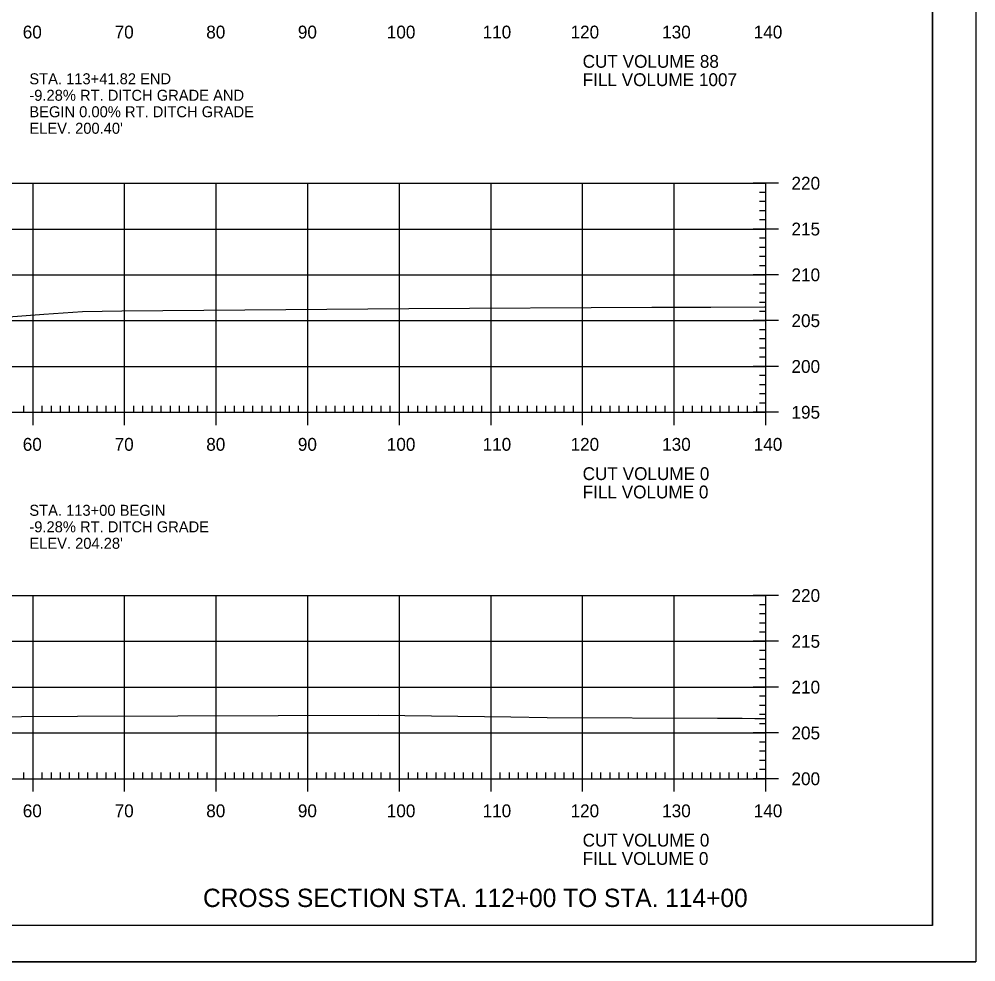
# Model space of a CAD drawing. Extents: x 1312042 to 1371461, y 379929 to 1834241.
# Drawn here: x 1371356.8 to 1371461.2, y 379928.9 to 380031.8 of the extents above; entities that cross this region are included whole.
import ezdxf

# ---------------------------------------------------------------- set-up
doc = ezdxf.new("R2010")
doc.units = 0
for name, color, linetype in [('R_Axis', 7, 'Continuous'), ('R_Axis Annot', 7, 'Continuous'), ('R_Border', 7, 'Continuous'), ('R_Draft', 7, 'Continuous'), ('R_Drive', 7, 'Continuous'), ('R_Exist Surface', 7, 'Continuous'), ('R_Grid', 7, 'Continuous'), ('R_No Plot', 7, 'Continuous')]:
    doc.layers.add(name, color=color, linetype=linetype)

msp = doc.modelspace()

# ---------------------------------------------------------------- linework, layer by layer
at = {"layer": 'R_Axis'}
for p, q in [((1371439.68, 380013.91), (1371436.88, 380013.91)), ((1371438.28, 379988.91), (1371438.28, 380013.91)), ((1371438.28, 380012.91), (1371437.58, 380012.91)), ((1371438.28, 380011.91), (1371437.58, 380011.91)), ((1371438.28, 380010.91), (1371437.58, 380010.91)), ((1371438.28, 380009.91), (1371437.58, 380009.91)), ((1371439.68, 380008.91), (1371436.88, 380008.91)), ((1371438.28, 380007.91), (1371437.58, 380007.91)), ((1371438.28, 380006.91), (1371437.58, 380006.91)), ((1371438.28, 380005.91), (1371437.58, 380005.91)), ((1371438.28, 380004.91), (1371437.58, 380004.91)), ((1371439.68, 380003.91), (1371436.88, 380003.91)), ((1371438.28, 380002.91), (1371437.58, 380002.91)), ((1371438.28, 380001.91), (1371437.58, 380001.91)), ((1371438.28, 380000.91), (1371437.58, 380000.91)), ((1371438.28, 379999.91), (1371437.58, 379999.91)), ((1371439.68, 379998.91), (1371436.88, 379998.91)), ((1371438.28, 379997.91), (1371437.58, 379997.91)), ((1371438.28, 379996.91), (1371437.58, 379996.91)), ((1371438.28, 379995.91), (1371437.58, 379995.91)), ((1371439.68, 379993.91), (1371436.88, 379993.91)), ((1371438.28, 379994.91), (1371437.58, 379994.91)), ((1371438.28, 379992.91), (1371437.58, 379992.91)), ((1371438.28, 379991.91), (1371437.58, 379991.91)), ((1371438.28, 379990.91), (1371437.58, 379990.91)), ((1371358.28, 379987.51), (1371358.28, 379990.31)), ((1371368.28, 379987.51), (1371368.28, 379990.31)), ((1371378.28, 379987.51), (1371378.28, 379990.31)), ((1371388.28, 379987.51), (1371388.28, 379990.31)), ((1371398.28, 379987.51), (1371398.28, 379990.31)), ((1371408.28, 379987.51), (1371408.28, 379990.31)), ((1371418.28, 379987.51), (1371418.28, 379990.31)), ((1371428.28, 379987.51), (1371428.28, 379990.31)), ((1371438.28, 379989.91), (1371437.58, 379989.91)), ((1371438.28, 379987.51), (1371438.28, 379990.31)), ((1371158.28, 379988.91), (1371438.28, 379988.91)), ((1371357.28, 379988.91), (1371357.28, 379989.61)), ((1371359.28, 379988.91), (1371359.28, 379989.61)), ((1371360.28, 379988.91), (1371360.28, 379989.61)), ((1371361.28, 379988.91), (1371361.28, 379989.61)), ((1371362.28, 379988.91), (1371362.28, 379989.61)), ((1371363.28, 379988.91), (1371363.28, 379989.61)), ((1371364.28, 379988.91), (1371364.28, 379989.61)), ((1371365.28, 379988.91), (1371365.28, 379989.61)), ((1371366.28, 379988.91), (1371366.28, 379989.61)), ((1371367.28, 379988.91), (1371367.28, 379989.61)), ((1371369.28, 379988.91), (1371369.28, 379989.61)), ((1371370.28, 379988.91), (1371370.28, 379989.61)), ((1371371.28, 379988.91), (1371371.28, 379989.61)), ((1371372.28, 379988.91), (1371372.28, 379989.61)), ((1371373.28, 379988.91), (1371373.28, 379989.61)), ((1371374.28, 379988.91), (1371374.28, 379989.61)), ((1371375.28, 379988.91), (1371375.28, 379989.61)), ((1371376.28, 379988.91), (1371376.28, 379989.61)), ((1371377.28, 379988.91), (1371377.28, 379989.61)), ((1371379.28, 379988.91), (1371379.28, 379989.61)), ((1371380.28, 379988.91), (1371380.28, 379989.61)), ((1371381.28, 379988.91), (1371381.28, 379989.61)), ((1371382.28, 379988.91), (1371382.28, 379989.61)), ((1371383.28, 379988.91), (1371383.28, 379989.61)), ((1371384.28, 379988.91), (1371384.28, 379989.61)), ((1371385.28, 379988.91), (1371385.28, 379989.61)), ((1371386.28, 379988.91), (1371386.28, 379989.61)), ((1371387.28, 379988.91), (1371387.28, 379989.61)), ((1371389.28, 379988.91), (1371389.28, 379989.61)), ((1371390.28, 379988.91), (1371390.28, 379989.61)), ((1371391.28, 379988.91), (1371391.28, 379989.61)), ((1371392.28, 379988.91), (1371392.28, 379989.61)), ((1371393.28, 379988.91), (1371393.28, 379989.61)), ((1371394.28, 379988.91), (1371394.28, 379989.61)), ((1371395.28, 379988.91), (1371395.28, 379989.61)), ((1371396.28, 379988.91), (1371396.28, 379989.61)), ((1371397.28, 379988.91), (1371397.28, 379989.61)), ((1371399.28, 379988.91), (1371399.28, 379989.61)), ((1371400.28, 379988.91), (1371400.28, 379989.61)), ((1371401.28, 379988.91), (1371401.28, 379989.61)), ((1371402.28, 379988.91), (1371402.28, 379989.61)), ((1371403.28, 379988.91), (1371403.28, 379989.61)), ((1371404.28, 379988.91), (1371404.28, 379989.61)), ((1371405.28, 379988.91), (1371405.28, 379989.61)), ((1371406.28, 379988.91), (1371406.28, 379989.61)), ((1371407.28, 379988.91), (1371407.28, 379989.61)), ((1371409.28, 379988.91), (1371409.28, 379989.61)), ((1371410.28, 379988.91), (1371410.28, 379989.61)), ((1371411.28, 379988.91), (1371411.28, 379989.61)), ((1371412.28, 379988.91), (1371412.28, 379989.61)), ((1371413.28, 379988.91), (1371413.28, 379989.61)), ((1371414.28, 379988.91), (1371414.28, 379989.61)), ((1371415.28, 379988.91), (1371415.28, 379989.61)), ((1371416.28, 379988.91), (1371416.28, 379989.61)), ((1371417.28, 379988.91), (1371417.28, 379989.61)), ((1371419.28, 379988.91), (1371419.28, 379989.61)), ((1371420.28, 379988.91), (1371420.28, 379989.61)), ((1371421.28, 379988.91), (1371421.28, 379989.61)), ((1371422.28, 379988.91), (1371422.28, 379989.61)), ((1371423.28, 379988.91), (1371423.28, 379989.61)), ((1371424.28, 379988.91), (1371424.28, 379989.61)), ((1371425.28, 379988.91), (1371425.28, 379989.61)), ((1371426.28, 379988.91), (1371426.28, 379989.61)), ((1371427.28, 379988.91), (1371427.28, 379989.61)), ((1371429.28, 379988.91), (1371429.28, 379989.61)), ((1371430.28, 379988.91), (1371430.28, 379989.61)), ((1371431.28, 379988.91), (1371431.28, 379989.61)), ((1371432.28, 379988.91), (1371432.28, 379989.61)), ((1371433.28, 379988.91), (1371433.28, 379989.61)), ((1371434.28, 379988.91), (1371434.28, 379989.61)), ((1371435.28, 379988.91), (1371435.28, 379989.61)), ((1371436.28, 379988.91), (1371436.28, 379989.61)), ((1371439.68, 379988.91), (1371436.88, 379988.91)), ((1371437.28, 379988.91), (1371437.28, 379989.61)), ((1371439.68, 379968.91), (1371436.88, 379968.91)), ((1371438.28, 379948.91), (1371438.28, 379968.91)), ((1371438.28, 379967.91), (1371437.58, 379967.91)), ((1371438.28, 379966.91), (1371437.58, 379966.91)), ((1371438.28, 379965.91), (1371437.58, 379965.91)), ((1371438.28, 379964.91), (1371437.58, 379964.91)), ((1371439.68, 379963.91), (1371436.88, 379963.91)), ((1371438.28, 379962.91), (1371437.58, 379962.91)), ((1371438.28, 379961.91), (1371437.58, 379961.91)), ((1371438.28, 379960.91), (1371437.58, 379960.91)), ((1371438.28, 379959.91), (1371437.58, 379959.91)), ((1371439.68, 379958.91), (1371436.88, 379958.91)), ((1371438.28, 379957.91), (1371437.58, 379957.91)), ((1371438.28, 379956.91), (1371437.58, 379956.91)), ((1371438.28, 379955.91), (1371437.58, 379955.91)), ((1371438.28, 379954.91), (1371437.58, 379954.91)), ((1371439.68, 379953.91), (1371436.88, 379953.91)), ((1371438.28, 379952.91), (1371437.58, 379952.91)), ((1371438.28, 379951.91), (1371437.58, 379951.91)), ((1371358.28, 379947.51), (1371358.28, 379950.31)), ((1371368.28, 379947.51), (1371368.28, 379950.31)), ((1371378.28, 379947.51), (1371378.28, 379950.31)), ((1371388.28, 379947.51), (1371388.28, 379950.31)), ((1371398.28, 379947.51), (1371398.28, 379950.31)), ((1371408.28, 379947.51), (1371408.28, 379950.31)), ((1371418.28, 379947.51), (1371418.28, 379950.31)), ((1371428.28, 379947.51), (1371428.28, 379950.31)), ((1371438.28, 379950.91), (1371437.58, 379950.91)), ((1371438.28, 379947.51), (1371438.28, 379950.31)), ((1371357.28, 379948.91), (1371357.28, 379949.61)), ((1371359.28, 379948.91), (1371359.28, 379949.61)), ((1371360.28, 379948.91), (1371360.28, 379949.61)), ((1371361.28, 379948.91), (1371361.28, 379949.61)), ((1371362.28, 379948.91), (1371362.28, 379949.61)), ((1371363.28, 379948.91), (1371363.28, 379949.61)), ((1371364.28, 379948.91), (1371364.28, 379949.61)), ((1371365.28, 379948.91), (1371365.28, 379949.61)), ((1371366.28, 379948.91), (1371366.28, 379949.61)), ((1371367.28, 379948.91), (1371367.28, 379949.61)), ((1371369.28, 379948.91), (1371369.28, 379949.61)), ((1371370.28, 379948.91), (1371370.28, 379949.61)), ((1371371.28, 379948.91), (1371371.28, 379949.61)), ((1371372.28, 379948.91), (1371372.28, 379949.61)), ((1371373.28, 379948.91), (1371373.28, 379949.61)), ((1371374.28, 379948.91), (1371374.28, 379949.61)), ((1371375.28, 379948.91), (1371375.28, 379949.61)), ((1371376.28, 379948.91), (1371376.28, 379949.61)), ((1371377.28, 379948.91), (1371377.28, 379949.61)), ((1371379.28, 379948.91), (1371379.28, 379949.61)), ((1371380.28, 379948.91), (1371380.28, 379949.61)), ((1371381.28, 379948.91), (1371381.28, 379949.61)), ((1371382.28, 379948.91), (1371382.28, 379949.61)), ((1371383.28, 379948.91), (1371383.28, 379949.61)), ((1371384.28, 379948.91), (1371384.28, 379949.61)), ((1371385.28, 379948.91), (1371385.28, 379949.61)), ((1371386.28, 379948.91), (1371386.28, 379949.61)), ((1371387.28, 379948.91), (1371387.28, 379949.61)), ((1371389.28, 379948.91), (1371389.28, 379949.61)), ((1371390.28, 379948.91), (1371390.28, 379949.61)), ((1371391.28, 379948.91), (1371391.28, 379949.61)), ((1371392.28, 379948.91), (1371392.28, 379949.61)), ((1371393.28, 379948.91), (1371393.28, 379949.61)), ((1371394.28, 379948.91), (1371394.28, 379949.61)), ((1371395.28, 379948.91), (1371395.28, 379949.61)), ((1371396.28, 379948.91), (1371396.28, 379949.61)), ((1371397.28, 379948.91), (1371397.28, 379949.61)), ((1371399.28, 379948.91), (1371399.28, 379949.61)), ((1371400.28, 379948.91), (1371400.28, 379949.61)), ((1371401.28, 379948.91), (1371401.28, 379949.61)), ((1371402.28, 379948.91), (1371402.28, 379949.61)), ((1371403.28, 379948.91), (1371403.28, 379949.61)), ((1371404.28, 379948.91), (1371404.28, 379949.61)), ((1371405.28, 379948.91), (1371405.28, 379949.61)), ((1371406.28, 379948.91), (1371406.28, 379949.61)), ((1371407.28, 379948.91), (1371407.28, 379949.61)), ((1371409.28, 379948.91), (1371409.28, 379949.61)), ((1371410.28, 379948.91), (1371410.28, 379949.61)), ((1371411.28, 379948.91), (1371411.28, 379949.61)), ((1371412.28, 379948.91), (1371412.28, 379949.61)), ((1371413.28, 379948.91), (1371413.28, 379949.61)), ((1371414.28, 379948.91), (1371414.28, 379949.61)), ((1371415.28, 379948.91), (1371415.28, 379949.61)), ((1371416.28, 379948.91), (1371416.28, 379949.61)), ((1371417.28, 379948.91), (1371417.28, 379949.61)), ((1371419.28, 379948.91), (1371419.28, 379949.61)), ((1371420.28, 379948.91), (1371420.28, 379949.61)), ((1371421.28, 379948.91), (1371421.28, 379949.61)), ((1371422.28, 379948.91), (1371422.28, 379949.61)), ((1371423.28, 379948.91), (1371423.28, 379949.61)), ((1371424.28, 379948.91), (1371424.28, 379949.61)), ((1371425.28, 379948.91), (1371425.28, 379949.61)), ((1371426.28, 379948.91), (1371426.28, 379949.61)), ((1371427.28, 379948.91), (1371427.28, 379949.61)), ((1371429.28, 379948.91), (1371429.28, 379949.61)), ((1371430.28, 379948.91), (1371430.28, 379949.61)), ((1371431.28, 379948.91), (1371431.28, 379949.61)), ((1371432.28, 379948.91), (1371432.28, 379949.61)), ((1371433.28, 379948.91), (1371433.28, 379949.61)), ((1371434.28, 379948.91), (1371434.28, 379949.61)), ((1371435.28, 379948.91), (1371435.28, 379949.61)), ((1371436.28, 379948.91), (1371436.28, 379949.61)), ((1371437.28, 379948.91), (1371437.28, 379949.61)), ((1371438.28, 379949.91), (1371437.58, 379949.91)), ((1371158.28, 379948.91), (1371438.28, 379948.91)), ((1371439.68, 379948.91), (1371436.88, 379948.91))]:
    msp.add_line(p, q, dxfattribs=at)
at = {"layer": 'R_Border'}
for q in [(1371456.46, 380138.37), (1371140.28, 379932.91)]:
    msp.add_line((1371456.46, 379932.91), q, dxfattribs=at)
at = {"layer": 'R_Exist Surface'}
for points in [[(1371350.76, 379998.98), (1371359.47, 379999.63), (1371363.7, 379999.91), (1371367.97, 379999.99), (1371399.3, 380000.24), (1371425.82, 380000.38), (1371430.98, 380000.38), (1371432.26, 380000.38), (1371438.09, 380000.43), (1371438.28, 380000.33)], [(1371346.49, 379955.49), (1371357.02, 379955.7), (1371363.13, 379955.74), (1371396.01, 379955.85), (1371410.43, 379955.66), (1371414.4, 379955.61), (1371432.99, 379955.54), (1371435.7, 379955.51), (1371437.08, 379955.5), (1371438.28, 379955.5)]]:
    msp.add_lwpolyline(points, dxfattribs=at)
at = {"layer": 'R_Grid'}
for p, q in [((1371158.28, 380013.91), (1371438.28, 380013.91)), ((1371358.28, 379988.91), (1371358.28, 380013.91)), ((1371368.28, 379988.91), (1371368.28, 380013.91)), ((1371378.28, 379988.91), (1371378.28, 380013.91)), ((1371388.28, 379988.91), (1371388.28, 380013.91)), ((1371398.28, 379988.91), (1371398.28, 380013.91)), ((1371408.28, 379988.91), (1371408.28, 380013.91)), ((1371418.28, 379988.91), (1371418.28, 380013.91)), ((1371428.28, 379988.91), (1371428.28, 380013.91)), ((1371438.28, 379988.91), (1371438.28, 380013.91)), ((1371158.28, 380008.91), (1371438.28, 380008.91)), ((1371158.28, 380003.91), (1371438.28, 380003.91)), ((1371158.28, 379998.91), (1371438.28, 379998.91)), ((1371158.28, 379993.91), (1371438.28, 379993.91)), ((1371158.28, 379988.91), (1371438.28, 379988.91)), ((1371158.28, 379968.91), (1371438.28, 379968.91)), ((1371358.28, 379948.91), (1371358.28, 379968.91)), ((1371368.28, 379948.91), (1371368.28, 379968.91)), ((1371378.28, 379948.91), (1371378.28, 379968.91)), ((1371388.28, 379948.91), (1371388.28, 379968.91)), ((1371398.28, 379948.91), (1371398.28, 379968.91)), ((1371408.28, 379948.91), (1371408.28, 379968.91)), ((1371418.28, 379948.91), (1371418.28, 379968.91)), ((1371428.28, 379948.91), (1371428.28, 379968.91)), ((1371438.28, 379948.91), (1371438.28, 379968.91)), ((1371158.28, 379963.91), (1371438.28, 379963.91)), ((1371158.28, 379958.91), (1371438.28, 379958.91)), ((1371158.28, 379953.91), (1371438.28, 379953.91)), ((1371158.28, 379948.91), (1371438.28, 379948.91))]:
    msp.add_line(p, q, dxfattribs=at)
at = {"layer": 'R_No Plot'}
msp.add_line((1371127.88, 379928.93), (1371461.21, 379928.93), dxfattribs=at)
for points in [[(1371127.87, 380142.26), (1371461.21, 380142.26), (1371461.21, 379928.93), (1371127.87, 379928.93)], [(1371374.2, 380138.37), (1371374.2, 380128.49), (1371409.93, 380128.49), (1371409.93, 380125.57), (1371433.13, 380125.57), (1371433.13, 380101.24), (1371456.46, 380101.24), (1371456.46, 379932.91), (1371140.28, 379932.91), (1371140.28, 380138.37)]]:
    msp.add_lwpolyline(points, close=True, dxfattribs=at)

# ---------------------------------------------------------------- texts
at = {"layer": 'R_Axis Annot'}
for s, p in [('60', (1371357.16, 380029.71)), ('70', (1371367.19, 380029.71)), ('80', (1371377.19, 380029.71)), ('90', (1371387.19, 380029.71)), ('100', (1371396.9, 380029.71)), ('110', (1371407.36, 380029.71)), ('120', (1371416.96, 380029.71)), ('130', (1371426.96, 380029.71)), ('140', (1371436.96, 380029.71)), ('CUT VOLUME 88', (1371418.28, 380026.51)), ('FILL VOLUME 1007', (1371418.28, 380024.51)), ('220', (1371441.08, 380013.21)), ('215', (1371441.08, 380008.21)), ('210', (1371441.08, 380003.21)), ('205', (1371441.08, 379998.21)), ('200', (1371441.08, 379993.21)), ('195', (1371441.08, 379988.21)), ('60', (1371357.16, 379984.71)), ('70', (1371367.19, 379984.71)), ('80', (1371377.19, 379984.71)), ('90', (1371387.19, 379984.71)), ('100', (1371396.9, 379984.71)), ('110', (1371407.36, 379984.71)), ('120', (1371416.96, 379984.71)), ('130', (1371426.96, 379984.71)), ('140', (1371436.96, 379984.71)), ('CUT VOLUME 0', (1371418.28, 379981.51)), ('FILL VOLUME 0', (1371418.28, 379979.51)), ('220', (1371441.08, 379968.21)), ('215', (1371441.08, 379963.21)), ('210', (1371441.08, 379958.21)), ('205', (1371441.08, 379953.21)), ('200', (1371441.08, 379948.21)), ('60', (1371357.16, 379944.71)), ('70', (1371367.19, 379944.71)), ('80', (1371377.19, 379944.71)), ('90', (1371387.19, 379944.71)), ('100', (1371396.9, 379944.71)), ('110', (1371407.36, 379944.71)), ('120', (1371416.96, 379944.71)), ('130', (1371426.96, 379944.71)), ('140', (1371436.96, 379944.71)), ('CUT VOLUME 0', (1371418.28, 379941.51)), ('FILL VOLUME 0', (1371418.28, 379939.51))]:
    msp.add_text(s, height=1.4, dxfattribs=at).set_placement(p)
at = {"layer": 'R_Draft'}
msp.add_text('CROSS SECTION STA. 112+00 TO STA. 114+00', height=2, dxfattribs=at).set_placement((1371376.84, 379934.91))
at = {"layer": 'R_Drive'}
for s, p in [('STA. 113+41.82 END', (1371357.88, 380024.71)), ('-9.28% RT. DITCH GRADE AND', (1371357.88, 380022.91)), ('BEGIN 0.00% RT. DITCH GRADE', (1371357.88, 380021.11)), ("ELEV. 200.40'", (1371357.88, 380019.31)), ('STA. 113+00 BEGIN', (1371357.88, 379977.61)), ('-9.28% RT. DITCH GRADE', (1371357.88, 379975.81)), ("ELEV. 204.28'", (1371357.88, 379974.01))]:
    msp.add_text(s, height=1.2, dxfattribs=at).set_placement(p)

doc.saveas('drawing.dxf')
